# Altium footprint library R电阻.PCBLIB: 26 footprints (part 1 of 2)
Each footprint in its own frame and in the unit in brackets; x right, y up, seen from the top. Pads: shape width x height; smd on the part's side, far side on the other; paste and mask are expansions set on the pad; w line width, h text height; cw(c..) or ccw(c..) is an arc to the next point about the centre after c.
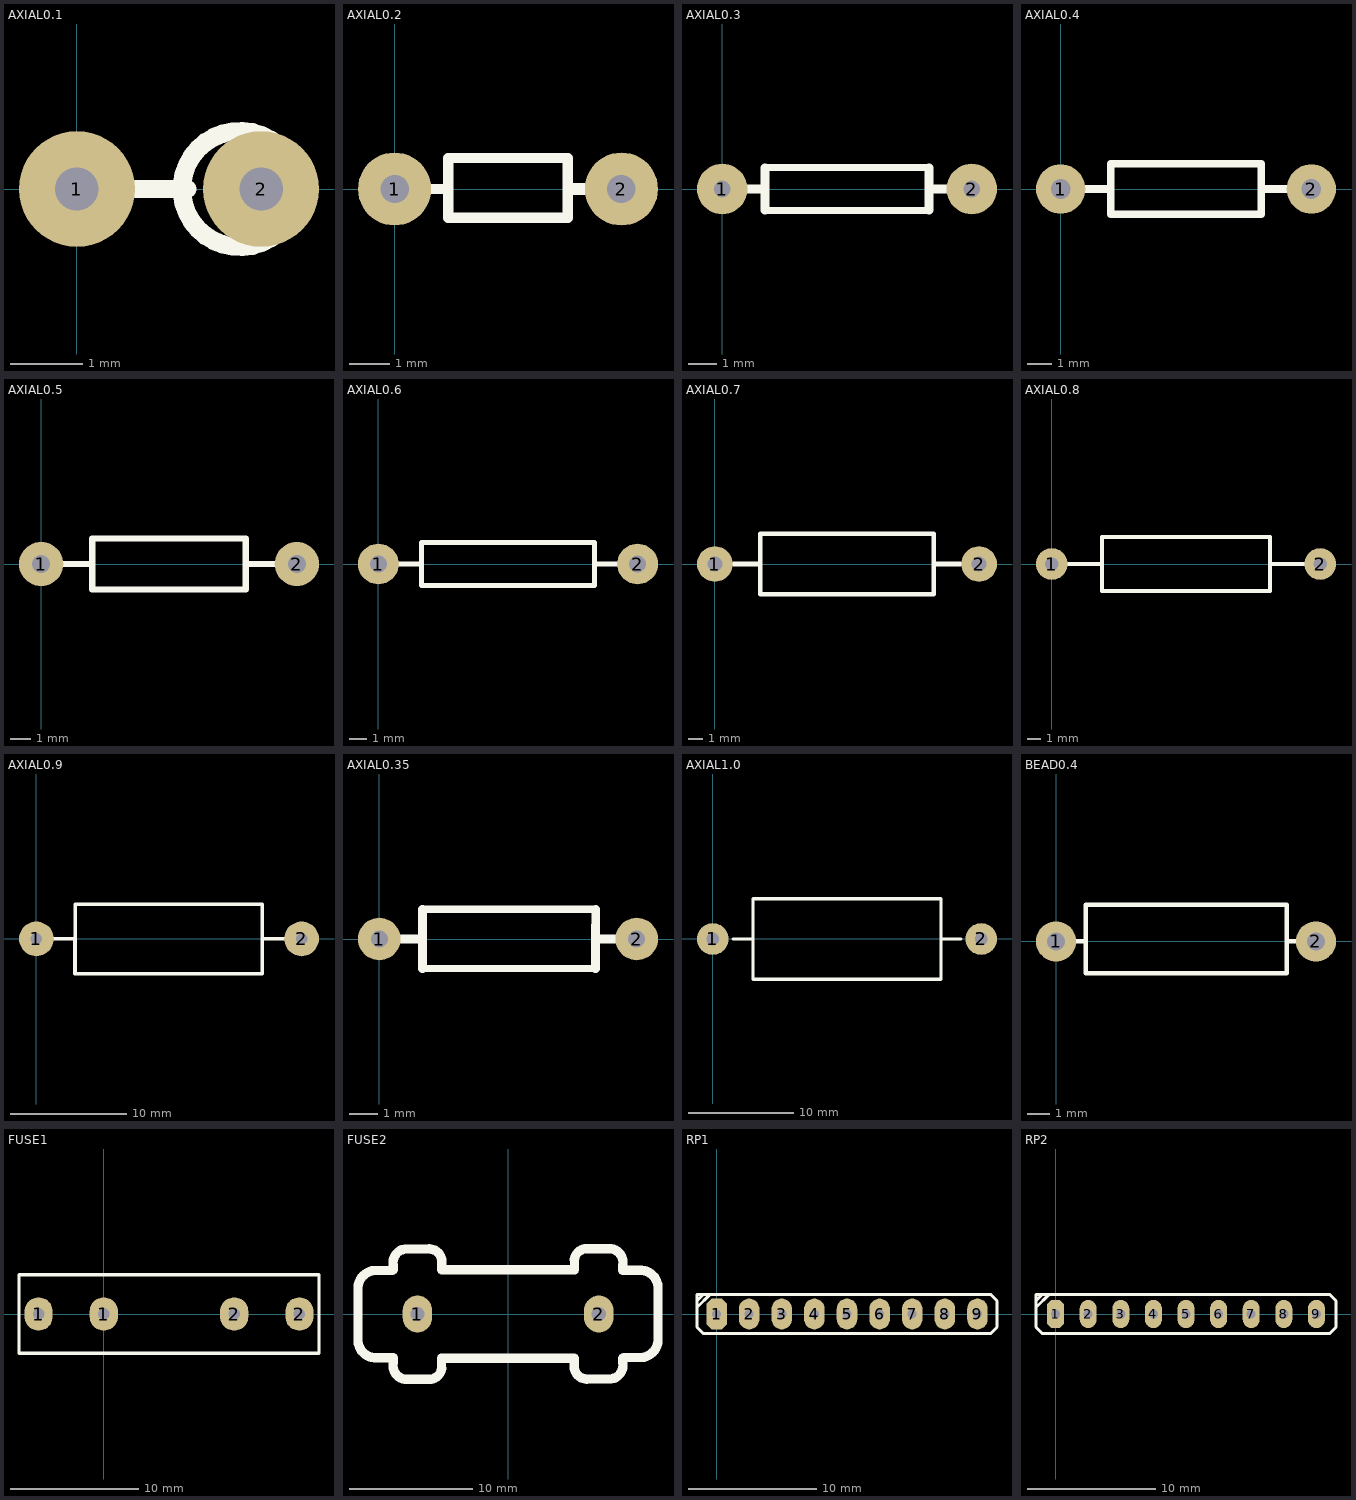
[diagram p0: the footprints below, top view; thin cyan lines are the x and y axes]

## AXIAL0.1 [mm]
pads (2):
  round 1.6 hole 0.6: 1(0,0) 2(2.54,0)
TopOverlay:
  circle w0.254: c2.248,0 r0.8
  lines w0.254: 0.508,0 1.524,0

## AXIAL0.2 [mm]
pads (2):
  round 1.8 hole 0.7: 1(0,0) 2(5.588,0)
TopOverlay:
  lines w0.254: 0.864,0 1.27,0 1.321,0.051 ; 3.785,0.762 4.267,0.762 ; 1.321,0.051 1.321,0.762 4.267,0.762 ; 1.321,0.051 1.321,-0.711 4.267,-0.711 ; 4.267,-0.711 4.267,0.762 ; 4.267,-0.711 4.267,0.762
  lines w0.305: 4.318,0 4.775,0

## AXIAL0.3 [mm]
pads (2):
  round 1.8 hole 0.6: 1(0,0) 2(8.89,0)
TopOverlay:
  lines w0.254: 1.524,-0.762 7.366,-0.762 ; 1.524,0.762 7.366,0.762
  lines w0.305: 0.808,0 1.524,0 ; 1.524,-0.762 1.524,0.762 ; 7.366,-0.762 7.366,0 ; 7.366,0.762 7.366,0 ; 8.431,0 7.366,0

## AXIAL0.4 [mm]
pads (2):
  round 2 hole 0.8: 1(0,0) 2(10.16,0)
TopOverlay:
  lines w0.305: 1.016,0 2.032,0 ; 8.128,0 9.144,0 ; 2.032,-1.016 8.128,-1.016 8.128,1.016 2.032,1.016 2.032,-1.016

## AXIAL0.5 [mm]
pads (2):
  round 2.2 hole 0.9: 1(0,0) 2(12.7,0)
TopOverlay:
  lines w0.305: 1.016,0 2.54,0 ; 10.16,0 11.684,0 ; 2.54,-1.27 2.54,1.27 10.16,1.27 10.16,-1.27 2.54,-1.27

## AXIAL0.6 [mm]
pads (2):
  round 2.4 hole 1: 1(0,0) 2(15.24,0)
TopOverlay:
  lines w0.305: 1.016,0 2.54,0 ; 12.7,0 14.224,0 ; 2.54,-1.27 12.7,-1.27 12.7,1.27 2.54,1.27 2.54,-1.27

## AXIAL0.7 [mm]
pads (2):
  round 2.4 hole 1: 1(0,0) 2(17.78,0)
TopOverlay:
  lines w0.305: 1.27,0 3.048,0 ; 14.732,0 16.51,0 ; 3.048,-2.032 14.732,-2.032 14.732,2.032 3.048,2.032 3.048,-2.032

## AXIAL0.8 [mm]
pads (2):
  round 2.4 hole 1: 1(0,0) 2(20.32,0)
TopOverlay:
  lines w0.305: 1.27,0 3.81,0 ; 16.51,0 19.05,0 ; 3.81,-2.032 16.51,-2.032 16.51,2.032 3.81,2.032 3.81,-2.032

## AXIAL0.9 [mm]
pads (2):
  round 3 hole 1: 1(0,0) 2(22.86,0)
TopOverlay:
  lines w0.305: 1.499,0 3.327,0.025 ; 3.353,2.997 3.327,-3.003 19.456,-3.023 19.482,2.997 3.353,3 ; 19.456,0 21.361,0

## AXIAL0.35 [mm]
pads (2):
  round 1.5 hole 0.6: 1(0,0) 2(9.075,0)
TopOverlay:
  lines w0.254: 1.525,-1.05 7.62,-1.041 ; 1.525,1.05 7.625,1.05
  lines w0.305: 0.7,0 1.524,0 ; 1.525,-1.05 1.525,1.05 ; 7.62,-1.041 7.62,0 ; 7.625,1.05 7.62,0 ; 8.636,0 7.62,0

## AXIAL1.0 [mm]
pads (2):
  round 3 hole 1.2: 1(0,0) 2(25.4,0)
TopOverlay:
  lines w0.305: 1.905,0 3.81,0 ; 21.59,0 23.495,0 ; 3.81,-3.81 3.81,3.81 21.59,3.81 21.59,-3.81 3.81,-3.81

## BEAD0.4 [mm]
pads (2):
  round 1.8 hole 0.8: 1(0,0) 2(11.684,0)
TopOverlay:
  lines w0.2: 0.914,0 1.346,0 ; 10.363,0 10.82,0 ; 1.346,-1.429 1.346,1.651 10.363,1.651 10.363,-1.429 1.346,-1.429

## FUSE1 [mm]
pads (4):
  oval 2.2x2.6 hole 0.9: 1(-5.08,0) 1(0,0) 2(10.16,0) 2(15.24,0)
TopOverlay:
  lines w0.254: -6.236,3.048 16.764,3.048 16.764,2.54 16.764,-3.048 -6.604,-3.048 -6.604,3.048 -5.588,3.048

## FUSE2 [mm]
pads (2):
  oval 2.4x3 hole 1.16: 1(-7.366,0) 2(7.366,0)
TopOverlay:
  lines w0.762: -5.41,-4.42 -5.41,-3.6 -0.007,-3.6 5.369,-3.6 5.368,-4.394 ccw(c6.401,-4.242) 6.553,-5.275 8.382,-5.275 ccw(c8.204,-4.166) 9.313,-3.988 9.322,-3.6 9.391,-3.531 10.643,-3.531 ccw(c10.731,-2.095) 12.167,-2.184 12.167,2.21 ccw(c10.731,2.121) 10.643,3.556 9.313,3.556 9.313,4.013 ccw(c8.204,4.191) 8.382,5.3 6.553,5.3 ccw(c6.401,4.267) 5.368,4.42 ; -5.393,-4.42 cw(c-6.426,-4.267) -6.579,-5.3 -8.407,-5.3 cw(c-8.23,-4.191) -9.339,-4.013 -9.339,-3.556 -10.668,-3.556 cw(c-10.757,-2.121) -12.192,-2.21 -12.192,2.184 cw(c-10.757,2.095) -10.668,3.531 -9.417,3.531 -9.347,3.6 -9.339,3.988 cw(c-8.23,4.166) -8.407,5.275 -6.579,5.275 cw(c-6.426,4.242) -5.393,4.394 -5.394,3.6 -0.019,3.6 5.385,3.6 5.385,4.42

## RP1 [mm]
pads (9):
  oct 1.6x2.4 hole 0.7: 1(0,0)
  oval 1.6x2.4 hole 0.7: 2(2.54,0) 3(5.08,0) 4(7.62,0) 5(10.16,0) 6(12.7,0) 7(15.24,0) 8(17.78,0) 9(20.32,0)
TopOverlay:
  lines w0.254: -1.524,0.508 -0.508,1.524 ; -1.524,1.016 -1.524,-1.016 -1.016,-1.524 21.336,-1.524 21.844,-1.016 21.844,1.016 21.336,1.524 -1.016,1.524 ; -1.524,1.016 -1.016,1.524 ; -1.524,1.016 -1.524,1.524 -1.016,1.524

## RP2 [mm]
pads (9):
  oct 1.32x2.2 hole 0.7: 1(0,0)
  oval 1.32x2.2 hole 0.7: 2(2.54,0) 3(5.08,0) 4(7.62,0) 5(10.16,0) 6(12.7,0) 7(15.24,0) 8(17.78,0) 9(20.32,0)
TopOverlay:
  lines w0.254: -1.524,0.508 -0.508,1.524 ; -1.524,1.016 -1.524,1.524 -1.016,1.524 ; -1.524,1.016 -1.016,1.524 ; -1.524,1.016 -1.524,-1.016 -1.016,-1.524 21.336,-1.524 21.844,-1.016 21.844,1.016 21.336,1.524 -1.016,1.524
